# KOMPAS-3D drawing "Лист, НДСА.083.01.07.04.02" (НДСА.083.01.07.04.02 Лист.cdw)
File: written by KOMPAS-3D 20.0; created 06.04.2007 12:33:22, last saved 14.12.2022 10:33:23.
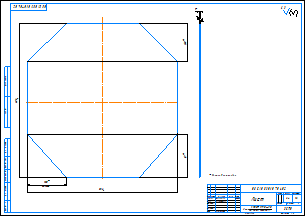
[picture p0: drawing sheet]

Sheet 1: A2, landscape

Document properties: Автор: Шубников; Организация: ЭСТО-Вакуум; Знак неуказанной шероховатости: 4; Параметр неуказанной шероховатости: 6,3; Полное имя файла: НДСА.083.01.07.04.02 Лист.m3d; PLM_CDWXDTO: <item xmlns="http://appius.ru/pdm" xmlns:xs="http://www.w3.org/2001/XMLSchema" xmlns:xsi="http://www.w3.org/2001/XMLSchema-instance" xsi:type="item">  <element xmlns:d2p1="http://v8.1c.ru/8.1/data/enterprise/current-config" xsi:type="d2p1:CatalogRef.aps_Элемен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; Масса: 2.40243; PDM_DOCXDTO: <item xmlns="http://appius.ru/pdm" xmlns:xs="http://www.w3.org/2001/XMLSchema" xmlns:xsi="http://www.w3.org/2001/XMLSchema-instance" xsi:type="item">  <element xmlns:d2p1="http://v8.1c.ru/8.1/data/enterprise/current-config" xsi:type="d2p1:CatalogRef.aps_Элемен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; PDM_ITEMXDTO: <item xmlns="http://appius.ru/pdm" xmlns:xs="http://www.w3.org/2001/XMLSchema" xmlns:xsi="http://www.w3.org/2001/XMLSchema-instance" xsi:type="item">  <element xmlns:d2p1="http://v8.1c.ru/8.1/data/enterprise/current-config" xsi:type="d2p1:CatalogRef.aps_Элемен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; PDM_DRAWINGXDTO: <item xmlns="http://appius.ru/pdm" xmlns:xs="http://www.w3.org/2001/XMLSchema" xmlns:xsi="http://www.w3.org/2001/XMLSchema-instance" xsi:type="item">  <element xmlns:d2p1="http://v8.1c.ru/8.1/data/enterprise/current-config" xsi:type="d2p1:CatalogRef.aps_Элемен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

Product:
- Part/product: Лист  | designation НДСА.083.01.07.04.02
    Материал: Лист$d1 ГОСТ 19904-90;10 ГОСТ 16523-97$ (density 7856 kg/m3)
    Масса: 2.40243
    additional columns: <item xmlns="http://appius.ru/pdm" xmlns:xs="http://www.w3.org/2001/XMLSchema" x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; <item xmlns="http://appius.ru/pdm" xmlns:xs="http://www.w3.org/2001/XMLSchema" x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; <item xmlns="http://appius.ru/pdm" xmlns:xs="http://www.w3.org/2001/XMLSchema" x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
    source file: НДСА.083.01.07.04.02 Лист.cdw

Title block, sheet 1: Наименование: Лист; designation: НДСА.083.01.07.04.02; Материал: Лист 1 ГОСТ 19904-90 10 ГОСТ 16523-97; Масса: 2,4; scale: 1:2; Количество листов документа: 1; organisation: ЭСТО; Форматы листов документа: A2; stored path: C:\Users\reznika\Desktop\Конвертация\Крышка камеры\Крышка камеры\УКРД.787.06.02.00.03 Лист.cdw; Разработал: Щербакова; Проверил: Горностаев; Утвердил: Белецкий; Разработал, date: 14.12.2022
Table, sheet 1:
  0;Material:VDE12371B5FDD453AAD3A0896F0FE5778;Sortament:VBE6DDF6ADAD111D69930000021274E8E^SortamentEx:VD7AC78F5EDAF4DB6A3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

Views: Проекционный вид 2, Проекционный вид 3
Referenced files in C:\Users\cherbakova\Desktop\Виноград\Новая папка (4)\: НДСА.083.01.07.04.02 Лист.m3d
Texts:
  НДСА.083.01.07.04.02  Лист
Dimensions and other numbers on the sheet: 603; 586; 150; 4места; 167; 1; 6,3; 1:2; 2,4; 14.12.2022

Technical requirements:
  * Размер для справок.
